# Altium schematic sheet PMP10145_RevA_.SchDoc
size 431 x 279 mm; Date: Not shown in title block; ApprovedBy: Not shown in title block; CheckedBy: Not shown in title block; Author: Not shown in title block; CompanyName: Not shown in title block; Engineer: Not shown in title block; Organization: Not shown in title block; Address1: Not shown in title block; Address2: Not shown in title block; Address3: Not shown in title block; Address4: Not shown in title block; DocumentNumber: 1; Revision: Use project parameter SCH_Rev; SheetNumber: 2; SheetTotal: 3; PageSetup: Record=PageOptions¦CenterHorizontal=True¦CenterVertical=True¦PrintScale=1.00¦XCorrection=1.00¦YCorrection=1.00¦PrintKind=0¦BorderSize=5000000¦LeftOffset=0¦BottomOffset=0¦Orientation=2¦PaperLength=1000¦PaperWidth=1000¦Scale=100¦PaperSource=15¦PrintQuality=600¦MediaType=1¦DitherType=10¦PaperKind=Letter¦PrintScaleMode=1
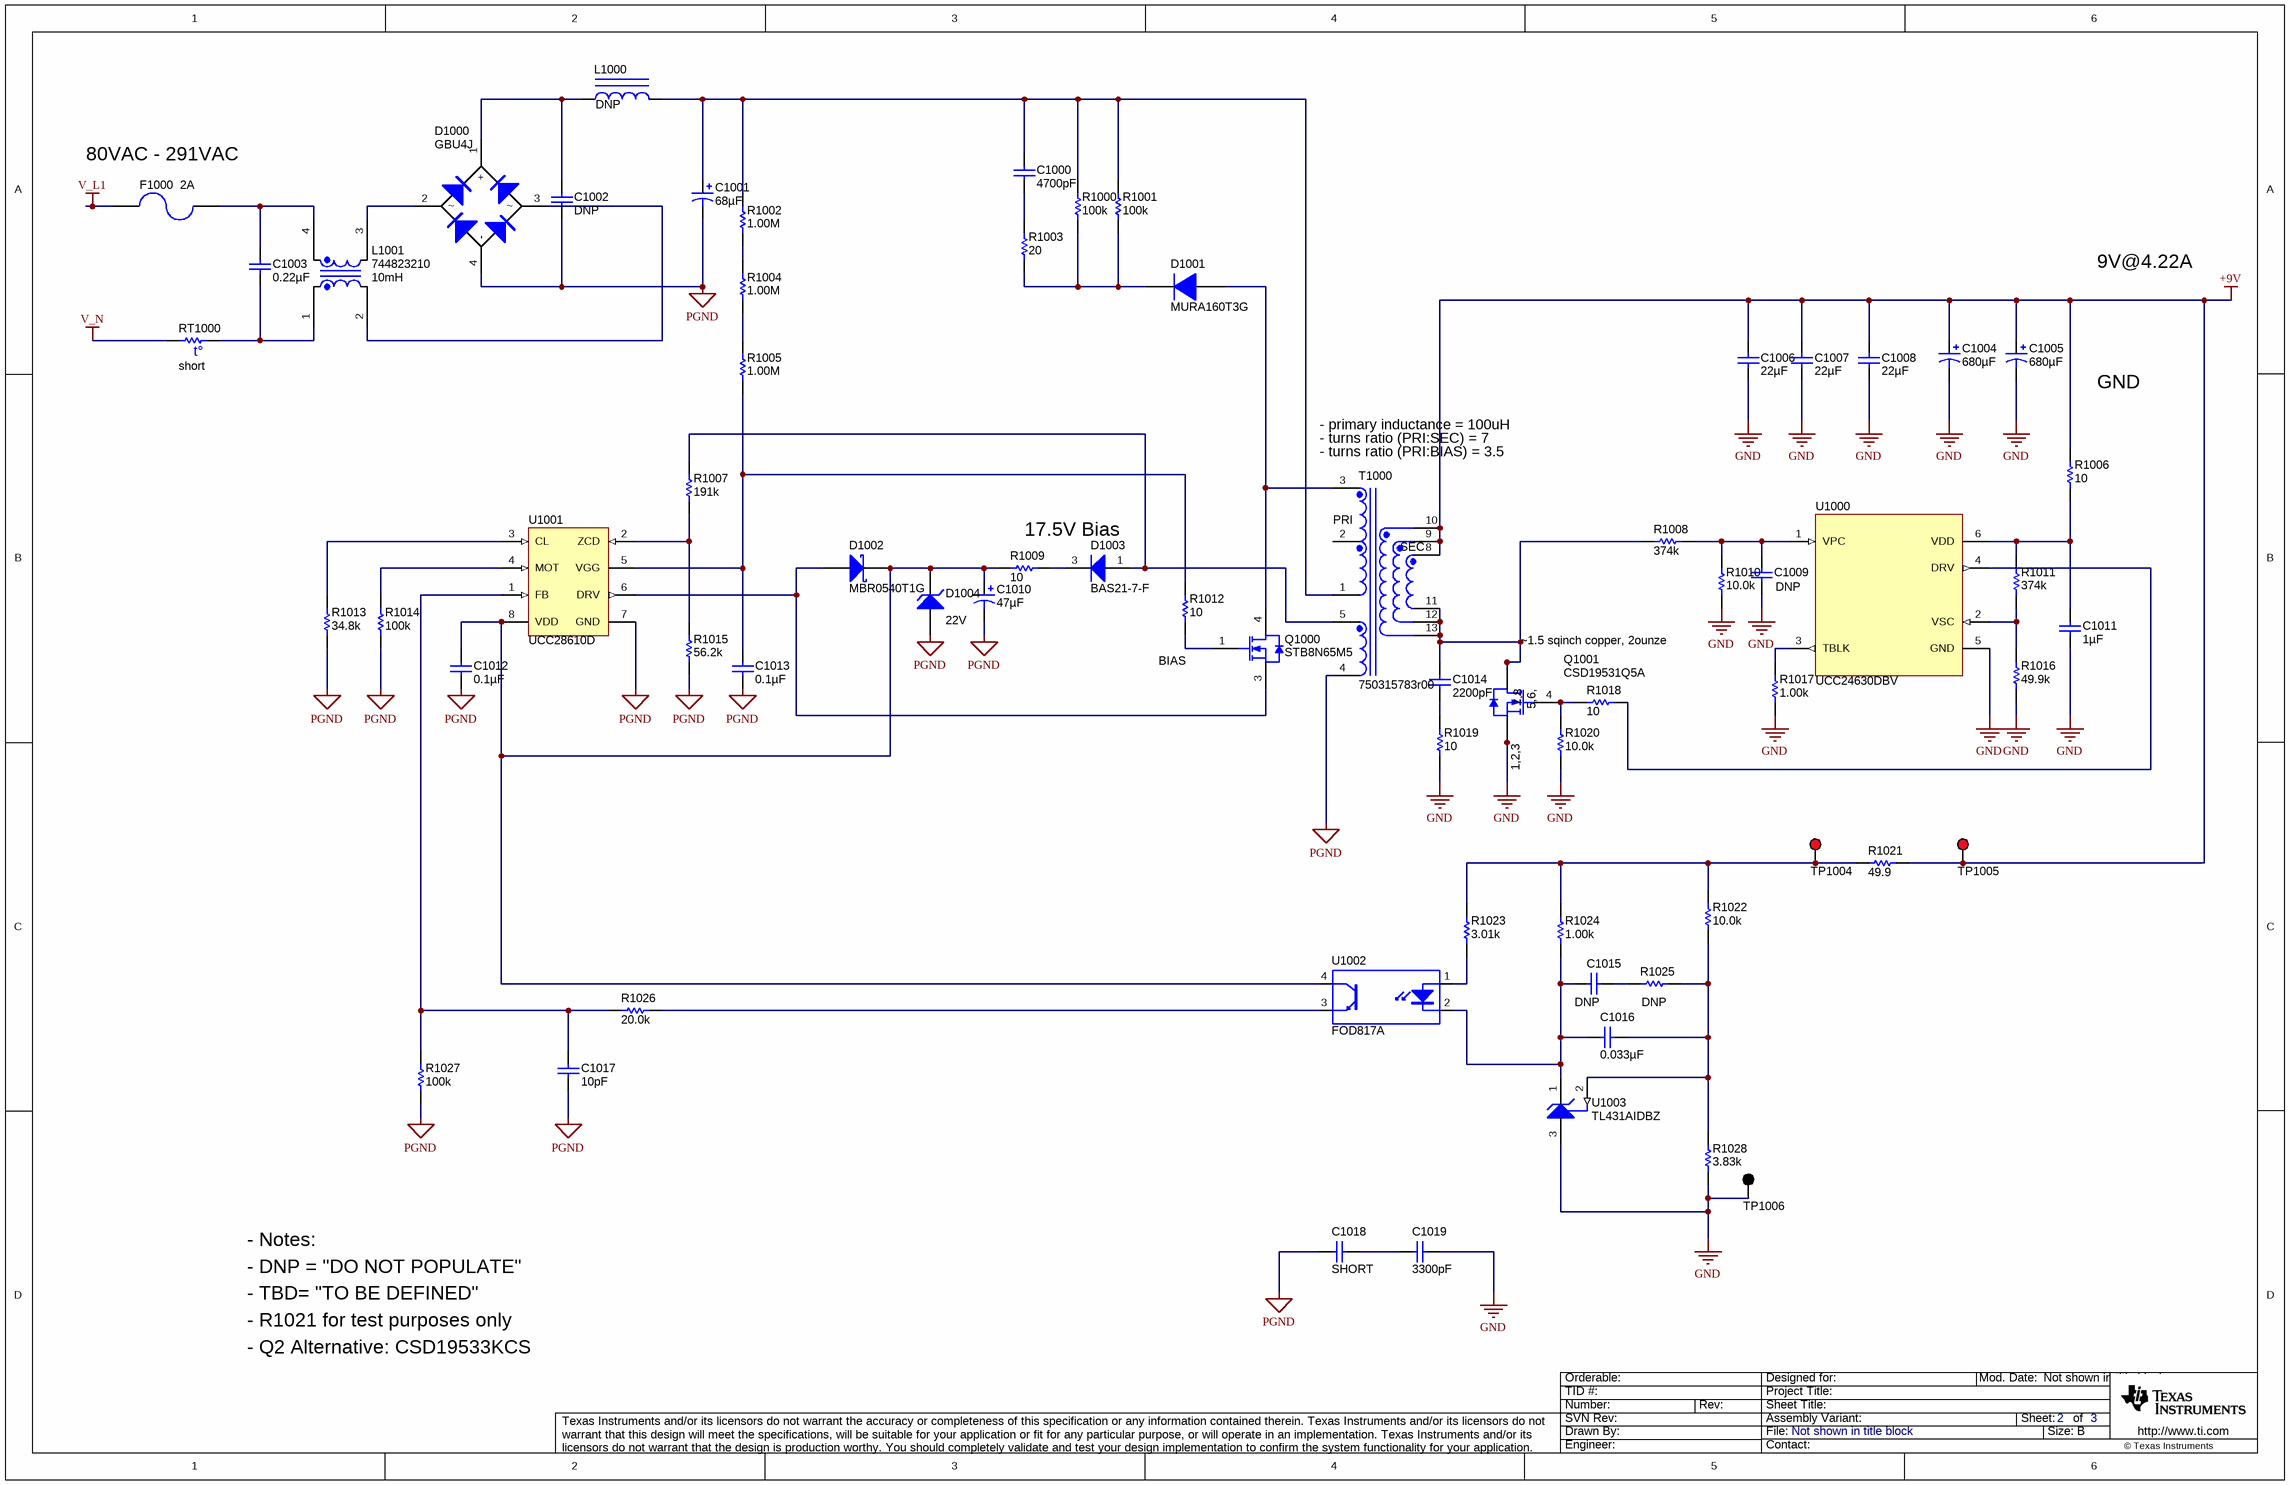
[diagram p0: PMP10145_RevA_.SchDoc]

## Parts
C1000  ValueDisplayed: 4700pF  [1206]  (hidden comment: C3216X7R2J472K)
C1001  ValueDisplayed: 68µF  [KXG_1800x3150]  (hidden comment: EKXG451ELL680MMN3S)
C1002  ValueDisplayed: DNP  [B32922_12.5mm]  (hidden comment: B32922C3224K)
C1003  ValueDisplayed: 0.22µF  [B32922_12.5mm]  (hidden comment: B32922C3224K)
C1004  ValueDisplayed: 680µF  [KZE_1250x2000]  (hidden comment: EKZE350ELL681MK20S)
C1005  ValueDisplayed: 680µF  [KZE_1250x2000]  (hidden comment: EKZE350ELL681MK20S)
C1006  ValueDisplayed: 22µF  [1210]  (hidden comment: GRM32ER71C226ME18L)
C1007  ValueDisplayed: 22µF  [1210]  (hidden comment: GRM32ER71C226ME18L)
C1008  ValueDisplayed: 22µF  [1210]  (hidden comment: GRM32ER71C226ME18L)
C1009  value DNP  [0603]  (hidden comment: Used in BOM report)
C1010  ValueDisplayed: 47µF  [SM_RADIAL_E]  (hidden comment: EEE-FC1V470P)
C1011  ValueDisplayed: 1µF  [0805_HV]  (hidden comment: GRM219R71E105KA88D)
C1012  ValueDisplayed: 0.1µF  [0805_HV]  (hidden comment: 08055C104JAT2A)
C1013  ValueDisplayed: 0.1µF  [0805_HV]  (hidden comment: 08055C104JAT2A)
C1014  ValueDisplayed: 2200pF  [0805_HV]  (hidden comment: GRM2165C2A222JA01D)
C1015  value DNP  [0805]  (hidden comment: Used in BOM report)
C1016  ValueDisplayed: 0.033µF  [0603]  (hidden comment: GRM188R71H333KA61D)
C1017  ValueDisplayed: 10pF  [0603]  (hidden comment: 06035A100JAT2A)
C1018  SHORT  [CD_1150x700x1550]
C1019  ValueDisplayed: 3300pF  [CD_1150x700x1550]  (hidden comment: DE1E3KX332MN4AP01F)
D1000  GBU4J  [GBU]
D1001  MURA160T3G  [SMA]
D1002  MBR0540T1G  [SOD-123]
D1003  BAS21-7-F  [SOT-23]
D1004  value 22V  [sod-323]  (hidden comment: MMSZ5251BS-7-F)
F1000  value 2A  [FUSE_372]  (hidden comment: 37212000001)
L1000  value DNP  [WE_TI_1014]  (hidden comment: 7447480331)
L1001  744823210  ValueDisplayed: 10mH  [IND_WE-CMB_M]
Q1000  STB8N65M5  [DDPAK]
Q1001  CSD19531Q5A  [TRANS_NexFET_Q5A]
R1000  ValueDisplayed: 100k  [2512]  (hidden comment: CRCW2512100KJNEG)
R1001  ValueDisplayed: 100k  [2512]  (hidden comment: CRCW2512100KJNEG)
R1002  ValueDisplayed: 1.00M  [0805_HV]  (hidden comment: CRCW08051M00FKEA)
R1003  ValueDisplayed: 20  [2010]  (hidden comment: CRCW201020R0JNEF)
R1004  ValueDisplayed: 1.00M  [0805_HV]  (hidden comment: CRCW08051M00FKEA)
R1005  ValueDisplayed: 1.00M  [0805_HV]  (hidden comment: CRCW08051M00FKEA)
R1006  ValueDisplayed: 10  [0805_HV]  (hidden comment: CRCW080510R0JNEA)
R1007  ValueDisplayed: 191k  [0603]  (hidden comment: CRCW0603191KFKEA)
R1008  ValueDisplayed: 374k  [0603]  (hidden comment: RC0603FR-07374KL)
R1009  ValueDisplayed: 10  [0805_HV]  (hidden comment: CRCW080510R0JNEA)
R1010  ValueDisplayed: 10.0k  [0603]  (hidden comment: RC0603FR-0710KL)
R1011  ValueDisplayed: 374k  [0603]  (hidden comment: RC0603FR-07374KL)
R1012  ValueDisplayed: 10  [0805_HV]  (hidden comment: CRCW080510R0JNEA)
R1013  ValueDisplayed: 34.8k  [0603]  (hidden comment: CRCW060334K8FKEA)
R1014  ValueDisplayed: 100k  [0603]  (hidden comment: CRCW0603100KFKEA)
R1015  ValueDisplayed: 56.2k  [0603]  (hidden comment: CRCW060356K2FKEA)
R1016  ValueDisplayed: 49.9k  [0603]  (hidden comment: CRCW060349K9FKEA)
R1017  ValueDisplayed: 1.00k  [0603]  (hidden comment: CRCW06031K00FKEA)
R1018  ValueDisplayed: 10  [0805_HV]  (hidden comment: CRCW080510R0JNEA)
R1019  ValueDisplayed: 10  [1206]  (hidden comment: CRCW120610R0JNEA)
R1020  ValueDisplayed: 10.0k  [0603]  (hidden comment: RC0603FR-0710KL)
R1021  ValueDisplayed: 49.9  [0603]  (hidden comment: CRCW060349R9FKEA)
R1022  ValueDisplayed: 10.0k  [0603]  (hidden comment: RC0603FR-0710KL)
R1023  ValueDisplayed: 3.01k  [0603]  (hidden comment: RC0603FR-073K01L)
R1024  ValueDisplayed: 1.00k  [0603]  (hidden comment: CRCW06031K00FKEA)
R1025  value DNP  [0603]  (hidden comment: Used in BOM report)
R1026  ValueDisplayed: 20.0k  [0603]  (hidden comment: CRCW060320K0FKEA)
R1027  ValueDisplayed: 100k  [0603]  (hidden comment: CRCW0603100KFKEA)
R1028  ValueDisplayed: 3.83k  [0603]  (hidden comment: RC0603FR-073K83L)
RT1000  value short  [THERM_B57236S0]  (hidden comment: B57236S0100M000)
T1000  750315783r00  [Wurth_750315431]
TP1004  5000  [Keystone5000]  (value not drawn)
TP1005  5000  [Keystone5000]  (value not drawn)
TP1006  5001  [Keystone5001]  (value not drawn)
U1000  UCC24630DBV  [DBV0006A_N]
U1001  UCC28610D  [D0008A_N]
U1002  FOD817A  [DIP-4]
U1003  TL431AIDBZ  [DBZ0003A_N]

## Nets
+9V: C1004.1(+) C1005.1(+) C1006.1 C1007.1 C1008.1 R1006.2 R1021.1 T1000.8 T1000.9 T1000.10 TP1005.1
GND: C1004.2(-) C1005.2(-) C1006.2 C1007.2 C1008.2 C1009.2 C1011.2 C1019.1 Q1001.1(S) Q1001.2(S) Q1001.3(S) R1010.2 R1016.2 R1017.2 R1019.1 R1020.2 R1028.1 TP1006.1 U1000.5(GND) U1003.3(ANODE)
PGND: C1001.2(-) C1002.2 C1010.2(-) C1012.2 C1013.2 C1017.2 C1018.2 D1000.4(-) D1004.2(A) R1013.1 R1014.1 R1015.1 R1027.1 T1000.4 U1001.7(GND)
V_L1: F1000.2
V_N: RT1000.1
NetC1000_1: C1000.1 C1001.1(+) L1000.2 R1000.2 R1001.2 R1002.2 T1000.1
NetC1000_2: C1000.2 R1003.2
NetC1002_1: C1002.1 D1000.1(+) L1000.1
NetC1003_1: C1003.1 F1000.1 L1001.4
NetC1003_2: C1003.2 L1001.1 RT1000.2
NetC1009_1: C1009.1 R1008.1 R1010.1 U1000.1(VPC)
NetC1010_1: C1010.1(+) C1012.1 D1002.1(K) D1004.1(K) R1009.1 U1001.8(VDD) U1002.4(C)
NetC1011_1: C1011.1 R1006.1 R1011.1 U1000.6(VDD)
NetC1013_1: C1013.1 R1005.1 R1012.2 U1001.5(VGG)
NetC1014_1: C1014.1 Q1001.5(D) Q1001.6(D) Q1001.7(D) Q1001.8(D) Q1001.9(D) R1008.2 T1000.11 T1000.12 T1000.13
NetC1014_2: C1014.2 R1019.2
NetC1015_1: C1015.1 R1025.1
NetC1015_2: C1015.2 C1016.2 R1024.1 U1002.2(K) U1003.1(CATHODE)
NetC1016_1: C1016.1 R1022.1 R1025.2 R1028.2 U1003.2(REF)
NetC1017_1: C1017.1 R1026.1 R1027.2 U1001.1(FB)
NetC1018_1: C1018.1 C1019.2
NetD1000_2: D1000.2 L1001.3
NetD1000_3: D1000.3 L1001.2
NetD1001_1: D1001.1(K) R1000.1 R1001.1 R1003.1
NetD1001_2: D1001.2(A) Q1000.4(D) T1000.3
NetD1002_2: D1002.2(A) Q1000.3(S) U1001.6(DRV)
NetD1003_1: D1003.1(A) R1007.2 T1000.5
NetD1003_3: D1003.3(K) R1009.2
NetQ1000_1: Q1000.1(G) R1012.1
NetQ1001_4: Q1001.4(G) R1018.1 R1020.1
NetR1002_1: R1002.1 R1004.2
NetR1004_1: R1004.1 R1005.2
NetR1007_1: R1007.1 R1015.2 U1001.2(ZCD)
NetR1011_2: R1011.2 R1016.1 U1000.2(VSC)
NetR1013_2: R1013.2 U1001.3(CL)
NetR1014_2: R1014.2 U1001.4(MOT)
NetR1017_1: R1017.1 U1000.3(TBLK)
NetR1018_2: R1018.2 U1000.4(DRV)
NetR1021_2: R1021.2 R1022.2 R1023.2 R1024.2 TP1004.1
NetR1023_1: R1023.1 U1002.1(A)
NetR1026_2: R1026.2 U1002.3(E)

Not connected (* = marked no-connect by the designer): T1000 2

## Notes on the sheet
- (near F1000) 80VAC - 291VAC
- 9V@4.22A
- - primary inductance = 100uH
- GND
- (near T1000) - turns ratio (PRI:SEC) = 7
- (near T1000) - turns ratio (PRI:BIAS) = 3.5
- 17.5V Bias
- (near T1000) PRI
- (near T1000) SEC
- (near R1012) BIAS
- .5 sqinch copper, 2ounze
- - Notes:
- - DNP = "DO NOT POPULATE"
- - TBD= "TO BE DEFINED"
- - R1021 for test purposes only
- - Q2 Alternative: CSD19533KCS

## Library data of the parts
C1000 = C3216X7R2J472K: CAP, CERM, 4700 pF, 630 V, +/- 10%, X7R, 1206; Manufacturer: TDK; Polarized: N; CompType: Capacitor; Value: 4700pF; U/M: EA; Cap_F: 0.0000000047; Tolerance_%: 10; ESR_ohm: 0.0962; Value1: 0.0962 ohm; VDC_V: 630; Value2: 630V; TaMin_C: -55; TaMax_C: 125
C1001 = EKXG451ELL680MMN3S: CAP, AL, 68 µF, 450 V, +/- 20%,  ohm, TH; Manufacturer: Chemi-Con; Polarized: Y; CompType: Capacitor; Value: 68uF; U/M: EA; Cap_F: 0.000068; Tolerance_%: 20; Value1: Unknown; VDC_V: 450; Value2: 450V; IRMS_A: 0.63; TaMin_C: -25; TaMax_C: 105; Cap_Case: 18x31.5mm
C1002 C1003 = B32922C3224K: CAP, Film, 0.22 µF, 630 V, +/- 10%, TH; Manufacturer: EPCOS Inc; Polarized: N; CompType: Capacitor; Value: 0.22uF; U/M: EA; Cap_F: 0.00000022; Tolerance_%: 10; Value1: Unknown; VDC_V: 630; Value2: 630V; TaMax_C: 110
C1004 C1005 = EKZE350ELL681MK20S: CAP, AL, 680 µF, 35 V, +/- 20%, 0.021 ohm, TH; Manufacturer: Chemi-Con; Polarized: Y; CompType: Capacitor; Value: 680uF; U/M: EA; Cap_F: 0.00068; Tolerance_%: 20; VDC_V: 35; Value2: 35V; ESR_ohm: 0.021; IRMS_A: 2.36; TaMin_C: -40; TaMax_C: 105; Cap_Case: 12.5x20mm
C1006-C1008 = GRM32ER71C226ME18L: CAP, CERM, 22 µF, 16 V, +/- 20%, X7R, 1210; Manufacturer: MuRata; Polarized: N; CompType: Capacitor; Value: 22uF; U/M: EA; Cap_F: 0.000022; Tolerance_%: 20; ESR_ohm: 0.003; Value1: 0.003 ohm; VDC_V: 16; Value2: 16V; IRMS_A: 3.2; TaMin_C: -55; TaMax_C: 125
C1009 C1015 = Capacitor: CAP, CERM, xxxF, xxV, [TempCo], xx%, [PackageReference]; Polarized: N; U/M: EA
C1010 = EEE-FC1V470P: CAP, AL, 47 µF, 35 V, +/- 20%, 0.4 ohm, SMD; Manufacturer: Panasonic; Polarized: Y; CompType: Capacitor; Value: 47uF; U/M: EA; Cap_F: 0.000047; Tolerance_%: 20; Value1: 0.4 ohm; VDC_V: 35; Value2: 35V; ESR_ohm: 0.4; IRMS_A: 0.15; TaMin_C: -40; TaMax_C: 105; Cap_Case: E
C1011 = GRM219R71E105KA88D: CAP, CERM, 1 µF, 25 V, +/- 10%, X7R, 0805; Manufacturer: MuRata; Polarized: N; CompType: Capacitor; Value: 1uF; U/M: EA; Cap_F: 0.000001; Tolerance_%: 10; Value1: Unknown; VDC_V: 25; Value2: 25V; TaMin_C: -55; TaMax_C: 125; Cap_Case: 0805
C1012 C1013 = 08055C104JAT2A: CAP, CERM, 0.1 µF, 50 V, +/- 5%, X7R, 0805; Manufacturer: AVX; Polarized: N; CompType: Capacitor; Value: 0.1uF; U/M: EA; Cap_F: 0.0000001; Tolerance_%: 5; ESR_ohm: 0.024; Value1: 0.024 ohm; VDC_V: 50; Value2: 50V; TaMin_C: -55; TaMax_C: 125; Cap_Case: 0805
C1014 = GRM2165C2A222JA01D: CAP, CERM, 2200 pF, 100 V, +/- 5%, C0G/NP0, 0805; Manufacturer: MuRata; Polarized: N; CompType: Capacitor; Value: 2200pF; U/M: EA; Cap_F: 0.0000000022; Tolerance_%: 5; Value1: Unknown; VDC_V: 100; Value2: 100V; TaMin_C: -55; TaMax_C: 125; Cap_Case: 0805
C1016 = GRM188R71H333KA61D: CAP, CERM, 0.033 µF, 50 V, +/- 10%, X7R, 0603; Manufacturer: MuRata; Polarized: N; CompType: Capacitor; Value: 0.033uF; U/M: EA; Cap_F: 0.000000033; Tolerance_%: 10; Value1: Unknown; VDC_V: 50; Value2: 50V; TaMin_C: -55; TaMax_C: 125
C1017 = 06035A100JAT2A: CAP, CERM, 10 pF, 50 V, +/- 5%, C0G/NP0, 0603; Manufacturer: AVX; Polarized: N; CompType: Capacitor; Value: 10pF; U/M: EA; Cap_F: 0.00000000001; Tolerance_%: 5; ESR_ohm: 0.403; Value1: 0.403 ohm; VDC_V: 50; Value2: 50V; TaMin_C: -55; TaMax_C: 125
C1018 = CD12-E2GA222MYGS: CAP, CERM, 2200 pF, 250 V, +/- 20%, E, TH, 2-Leads, Body 11.5x7mm, Pin Spacing 10mm; Manufacturer: TDK; Polarized: N; CompType: Capacitor; U/M: EA; Cap_F: 0.0000000022; Tolerance_%: 20; Value1: Unknown; VDC_V: 250; Value2: 250V; TaMin_C: -25; TaMax_C: 85; Cap_Case: 11.5x7x11.5mm; Ratings: X1Y1
C1019 = CD12-E2GA222MYGS: CAP, CERM, 3300 pF, 300 V, Y1; Manufacturer: TDK; Polarized: N; CompType: Capacitor; Value: 3300pF; U/M: EA; Cap_F: 0.0000000022; Tolerance_%: 20; Value1: Unknown; Value2: 300V; TempCo: E; TaMin_C: -25; TaMax_C: 85; Cap_Case: 11.5x7x11.5mm; Ratings: X1Y1
D1000 = GBU4K-E3/45: Diode, Switching-Bridge, 600 V; Manufacturer: Vishay-Semiconductor; U/M: EA; Vf_V: 1; Value: 600V; Value1: 4A; Value2: 1V; Io_A: 4; Vr_V: 800; TJmax_C: 150; RJC_CperW: 4.2
D1001 = MURA160T3G: Diode, Ultrafast, 600 V, 1 A, SMA; Manufacturer: ON Semiconductor; U/M: EA; Vf_V: 1.05; Value: 600V; Value1: 1A; Value2: 1.05V; Io_A: 1; Vr_V: 600; TJmax_C: 175
D1002 = MBR0540T1G: Diode, Schottky, 40 V, 0.5 A, SOD-123; Manufacturer: ON Semiconductor; U/M: EA; Vf_V: 0.51; Value: 40V; Value1: 0.5A; Value2: 0.51V; Io_A: 0.5; Vr_V: 40; TJmax_C: 150; RJC_CperW: 118
D1003 = BAS21-7-F: Diode, Switching, 200 V, 0.2 A, SOT-23; Manufacturer: Diodes Inc.; U/M: EA; Vf_V: 1.25; Value: 200V; Value1: 0.2A; Value2: 1.25V; Io_A: 0.2; Vr_V: 200; TJmax_C: 150; RJC_CperW: 500
D1004 = MMSZ5251BS-7-F: Diode, Zener, 22 V, 200 mW, SOD-323; Manufacturer: Diodes Inc.; SymbolCreator: a0412235; U/M: EA; Power_W: 0.2; Vz_V: 22; Value1: 0.2W; RJA_CperW: 350
F1000 = 37212000001: Fuse, 2 A, 250 V, TH; Manufacturer: Littelfuse; U/M: EA; OpeningTime_200%_max: 2; VDC_V: 250; Vdrop: 0.085; Soldering_Wave_MaxTemp_C: 260; Soldering_Wave_MaxTime_s: 5
L1000 = 7447480331: Inductor, Wirewound, Ferrite, 330 µH, 1.4 A, 0.3 ohm, TH; Manufacturer: Wurth Elektronik; Ind_H: 330.0E-6; Imax_A: 1.4; Irms: 1.4A @ 40C rise; Isat: 1.6A @ 10% inductance drop; DCR_ohm: 0.3; Value1: 0.3 ohm; Value2: 1.4A
L1001 = 744823210: Coupled inductor, 10 mH, 2 A, 0.125 ohm, +/- 30%, TH; Manufacturer: Wurth Elektronik eiSos; SymbolCreator: a0412235; Ind_H: 10.0E-3; DCR_ohm: 0.125; Isat: 2; Tolerance_%: 30; Value: 10mH
Q1000 = STB8N65M5: MOSFET, N-CH, 710 V, 7 A, DDPAK; Manufacturer: STMicroelectronics; Alternate Manufacturer: None; U/M: EA; ChType: N; Value: 710V; VdsMax_V: 710; Value1: ? ohm; Value2: 15 nC; QgTyp_nC: 15; Vgs_V: 25; IdsMax_A: 7
Q1001 = CSD19531Q5A: MOSFET, N-CH, 100 V, 16 A, SON 5x6mm; Manufacturer: Texas Instruments; Alternate Manufacturer: None; U/M: EA; ChType: N; Value: 100V; VdsMax_V: 100; Value1: ? ohm; Value2: 36 nC; QgTyp_nC: 36; Vgs_V: 20; IdsMax_A: 16
R1000 R1001 = CRCW2512100KJNEG: RES, 100 k, 5%, 1 W, 2512; Manufacturer: Vishay-Dale; CompType: Resistor; Value: 100k; Res_ohm: 100000; Tolerance_%: 5; Power_W: 1; Value2: 1W; VDC_V: 500; TempCo: 200 ppm/C; EIA_Code: E24; U/M: EA
R1002 R1004 R1005 = CRCW08051M00FKEA: RES, 1.00 M, 1%, 0.125 W, 0805; Manufacturer: Vishay-Dale; CompType: Resistor; Value: 1.00Meg; Res_ohm: 1000000; Value_Code: 1M00; Tolerance_%: 1; Power_W: 0.125; Value2: 0.125W; VDC_V: 150; TempCo: 100 ppm/C; EIA_Code: E96; U/M: EA
R1003 = CRCW201020R0JNEF: RES, 20, 5%, 0.75 W, 2010; Manufacturer: Vishay-Dale; CompType: Resistor; Value: 20; Value_Code: 20R0; Tolerance_%: 5; Power_W: 0.75; Value2: 0.75W; VDC_V: 400; TempCo: 200 ppm/C; EIA_Code: E24; U/M: EA
R1006 R1009 R1012 R1018 = CRCW080510R0JNEA: RES, 10, 5%, 0.125 W, 0805; Manufacturer: Vishay-Dale; CompType: Resistor; Value: 10; Value_Code: 10R0; Tolerance_%: 5; Power_W: 0.125; Value2: 0.125W; VDC_V: 150; TempCo: 200 ppm/C; EIA_Code: E24; U/M: EA
R1007 = CRCW0603191KFKEA: RES, 191 k, 1%, 0.1 W, 0603; Manufacturer: Vishay-Dale; CompType: Resistor; Value: 191k; Res_ohm: 191000; Tolerance_%: 1; Power_W: 0.1; Value2: 0.1W; VDC_V: 75; TempCo: 100 ppm/C; EIA_Code: E96; U/M: EA
R1008 R1011 = RC0603FR-07374KL: RES, 374 k, 1%, 0.1 W, 0603; Manufacturer: Yageo America; CompType: Resistor; Value: 374k; Res_ohm: 374000; Tolerance_%: 1; Power_W: 0.1; Value2: 0.1W; VDC_V: 150; TempCo: 200 ppm/C; EIA_Code: E96; U/M: EA
R1010 R1020 R1022 = RC0603FR-0710KL: RES, 10.0 k, 1%, 0.1 W, 0603; Manufacturer: Yageo America; CompType: Resistor; Value: 10.0k; Res_ohm: 10000; Value_Code: 10k0; Tolerance_%: 1; Power_W: 0.1; Value2: 0.1W; VDC_V: 150; TempCo: 200 ppm/C; EIA_Code: E96; U/M: EA
R1013 = CRCW060334K8FKEA: RES, 34.8 k, 1%, 0.1 W, 0603; Manufacturer: Vishay-Dale; CompType: Resistor; Value: 34.8k; Res_ohm: 34800; Value_Code: 34k8; Tolerance_%: 1; Power_W: 0.1; Value2: 0.1W; VDC_V: 75; TempCo: 100 ppm/C; EIA_Code: E96; U/M: EA
R1014 R1027 = CRCW0603100KFKEA: RES, 100 k, 1%, 0.1 W, 0603; Manufacturer: Vishay-Dale; CompType: Resistor; Value: 100k; Res_ohm: 100000; Tolerance_%: 1; Power_W: 0.1; Value2: 0.1W; VDC_V: 75; TempCo: 100 ppm/C; EIA_Code: E96; U/M: EA
R1015 = CRCW060356K2FKEA: RES, 56.2 k, 1%, 0.1 W, 0603; Manufacturer: Vishay-Dale; CompType: Resistor; Value: 56.2k; Res_ohm: 56200; Value_Code: 56k2; Tolerance_%: 1; Power_W: 0.1; Value2: 0.1W; VDC_V: 75; TempCo: 100 ppm/C; EIA_Code: E96; U/M: EA
R1016 = CRCW060349K9FKEA: RES, 49.9 k, 1%, 0.1 W, 0603; Manufacturer: Vishay-Dale; CompType: Resistor; Value: 49.9k; Res_ohm: 49900; Value_Code: 49k9; Tolerance_%: 1; Power_W: 0.1; Value2: 0.1W; VDC_V: 75; TempCo: 100 ppm/C; EIA_Code: E96; U/M: EA
R1017 R1024 = CRCW06031K00FKEA: RES, 1.00 k, 1%, 0.1 W, 0603; Manufacturer: Vishay-Dale; CompType: Resistor; Value: 1.00k; Res_ohm: 1000; Value_Code: 1k00; Tolerance_%: 1; Power_W: 0.1; Value2: 0.1W; VDC_V: 75; TempCo: 100 ppm/C; EIA_Code: E96; U/M: EA
R1019 = CRCW120610R0JNEA: RES, 10, 5%, 0.25 W, 1206; Manufacturer: Vishay-Dale; CompType: Resistor; Value: 10; Value_Code: 10R0; Tolerance_%: 5; Power_W: 0.25; Value2: 0.25W; VDC_V: 200; TempCo: 200 ppm/C; EIA_Code: E24; U/M: EA
R1021 = CRCW060349R9FKEA: RES, 49.9, 1%, 0.1 W, 0603; Manufacturer: Vishay-Dale; CompType: Resistor; Value: 49.9; Value_Code: 49R9; Tolerance_%: 1; Power_W: 0.1; Value2: 0.1W; VDC_V: 75; TempCo: 100 ppm/C; EIA_Code: E96; U/M: EA
R1023 = RC0603FR-073K01L: RES, 3.01 k, 1%, 0.1 W, 0603; Manufacturer: Yageo America; CompType: Resistor; Value: 3.01k; Res_ohm: 3010; Value_Code: 3k01; Tolerance_%: 1; Power_W: 0.1; Value2: 0.1W; VDC_V: 150; TempCo: 200 ppm/C; EIA_Code: E96; U/M: EA
R1025 = Resistor: RES, xxx ohm, x%, xW, [PackageReference]; U/M: EA
R1026 = CRCW060320K0FKEA: RES, 20.0 k, 1%, 0.1 W, 0603; Manufacturer: Vishay-Dale; CompType: Resistor; Value: 20.0k; Res_ohm: 20000; Value_Code: 20k0; Tolerance_%: 1; Power_W: 0.1; Value2: 0.1W; VDC_V: 75; TempCo: 100 ppm/C; EIA_Code: E96; U/M: EA
R1028 = RC0603FR-073K83L: RES, 3.83 k, 1%, 0.1 W, 0603; Manufacturer: Yageo America; CompType: Resistor; Value: 3.83k; Res_ohm: 3830; Value_Code: 3k83; Tolerance_%: 1; Power_W: 0.1; Value2: 0.1W; VDC_V: 150; TempCo: 200 ppm/C; EIA_Code: E96; U/M: EA
RT1000 = B57236S0100M000: Thermistor NTC, 10 ohm, 20%, Disc_11.5mmx6mm; Manufacturer: EPCOS Inc; Tolerance_%: 20; Power_W: 2.1; TaMin_C: -55; TaMax_C: 170; U/M: EA
T1000 = 750315431: Transformer, 150uH, TH; Manufacturer: Wurth Elektronik; SymbolCreator: Altium; DCR_Ohm: 0.26; U/M: EA
TP1004 TP1005 = 5000: Test Point, Miniature, Red, TH; Manufacturer: Keystone; CompType: Test Point Loop; U/M: EA
TP1006 = 5001: Test Point, Miniature, Black, TH; Manufacturer: Keystone; CompType: Test Point Loop; U/M: EA
U1000 = UCC24630DBV: SYNCRONOUS RECTIFIER CONTROLLER WITH LOW POWER STANDBY, DBV0006A; Manufacturer: Texas Instruments; SymbolCreator: a0411947; CompType: IC; U/M: EA
U1001 = UCC28610D: Green-Mode Flyback Power Supply Controller with Discontinuous Current Control, -40 to +125 degC, 8-pin SOIC (D), Green (RoHS & no Sb/Br); Manufacturer: Texas Instruments; Alternate Manufacturer: None; Alternate PartNumber: Equivalent; Frequency(Max)(kHz): 130; Rating: Catalog; SubFamily: PWM Controller
U1002 = FOD817A: High Operating Temperature Phototransistor Optocoupler, DIP-4; Manufacturer: Fairchild Semiconductor; U/M: EA
U1003 = TL431AIDBZ: PRECISION PROGRAMMABLE REFERENCE, DBZ0003A; Manufacturer: Texas Instruments; SymbolCreator: a0412235; CompType: IC; U/M: EA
